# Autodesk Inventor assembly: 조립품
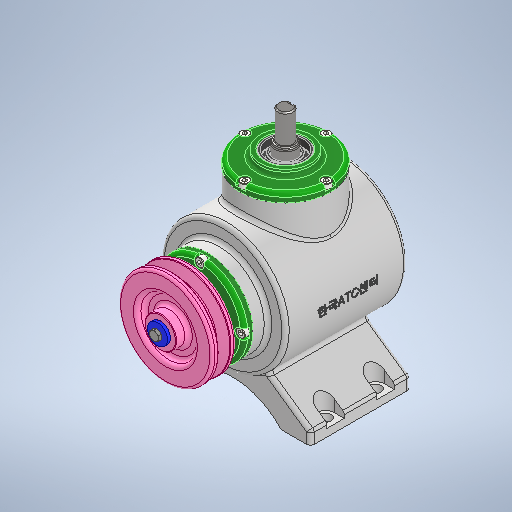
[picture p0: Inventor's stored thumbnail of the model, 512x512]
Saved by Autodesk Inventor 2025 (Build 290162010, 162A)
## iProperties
Created: 2024-07
Part Number: 조립품
Document SubType Name: Assembly
Designer: 학생
Author: 학생
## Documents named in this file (15)
- C:\Users\학생\Desktop\740709V1009\조립품.iam
- C:\Users\학생\Desktop\740709V1009\본체.ipt
- C:\Users\학생\Desktop\740709V1009\Ű 4 x 4 x 14\Ű 4 x 4 x 14.ipt
- C:\Users\학생\Desktop\740709V1009\Ű 5 x 5 x 14\Ű 5 x 5 x 14.ipt
- C:\Users\학생\Desktop\740709V1009\V-벨트풀리\V-벨트풀리.ipt
- C:\Users\학생\Desktop\740709V1009\메인 베벨기어\메인 베벨기어.ipt
- C:\Users\학생\Desktop\740709V1009\메인 축\메인 축.ipt
- C:\Users\학생\Desktop\740709V1009\베어링 6203\베어링 6203.ipt
- C:\Users\학생\Desktop\740709V1009\볼트 M4 x 10\볼트 M4 x 10.ipt
- C:\Users\학생\Desktop\740709V1009\서브 베벨기어\서브 베벨기어.ipt
- C:\Users\학생\Desktop\740709V1009\서브 축\서브 축.ipt
- C:\Users\학생\Desktop\740709V1009\오일실 17 x 32 x 8\오일실 17 x 32 x 8.ipt
- C:\Users\학생\Desktop\740709V1009\와셔 4 x 16\와셔 4 x 16.ipt
- C:\Users\학생\Desktop\740709V1009\육각볼트 M4 x 8\육각볼트 M4 x 8.ipt
- C:\Users\학생\Desktop\740709V1009\커버\커버.ipt
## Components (4 placed, 3 different names)
1. Ű 4 x 4 x 14:1 — 각도:8
2. Ű 5 x 5 x 14:1 — 각도:10
3. V-벨트풀리:1 — 각도:11
4. Ű 4 x 4 x 14:2 — 각도:11
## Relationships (3: Angle 3)
- 각도:8 [Angle]: Ű 4 x 4 x 14:1
- 각도:10 [Angle]: Ű 5 x 5 x 14:1
- 각도:11 [Angle]: V-벨트풀리:1 ↔ Ű 4 x 4 x 14:2
